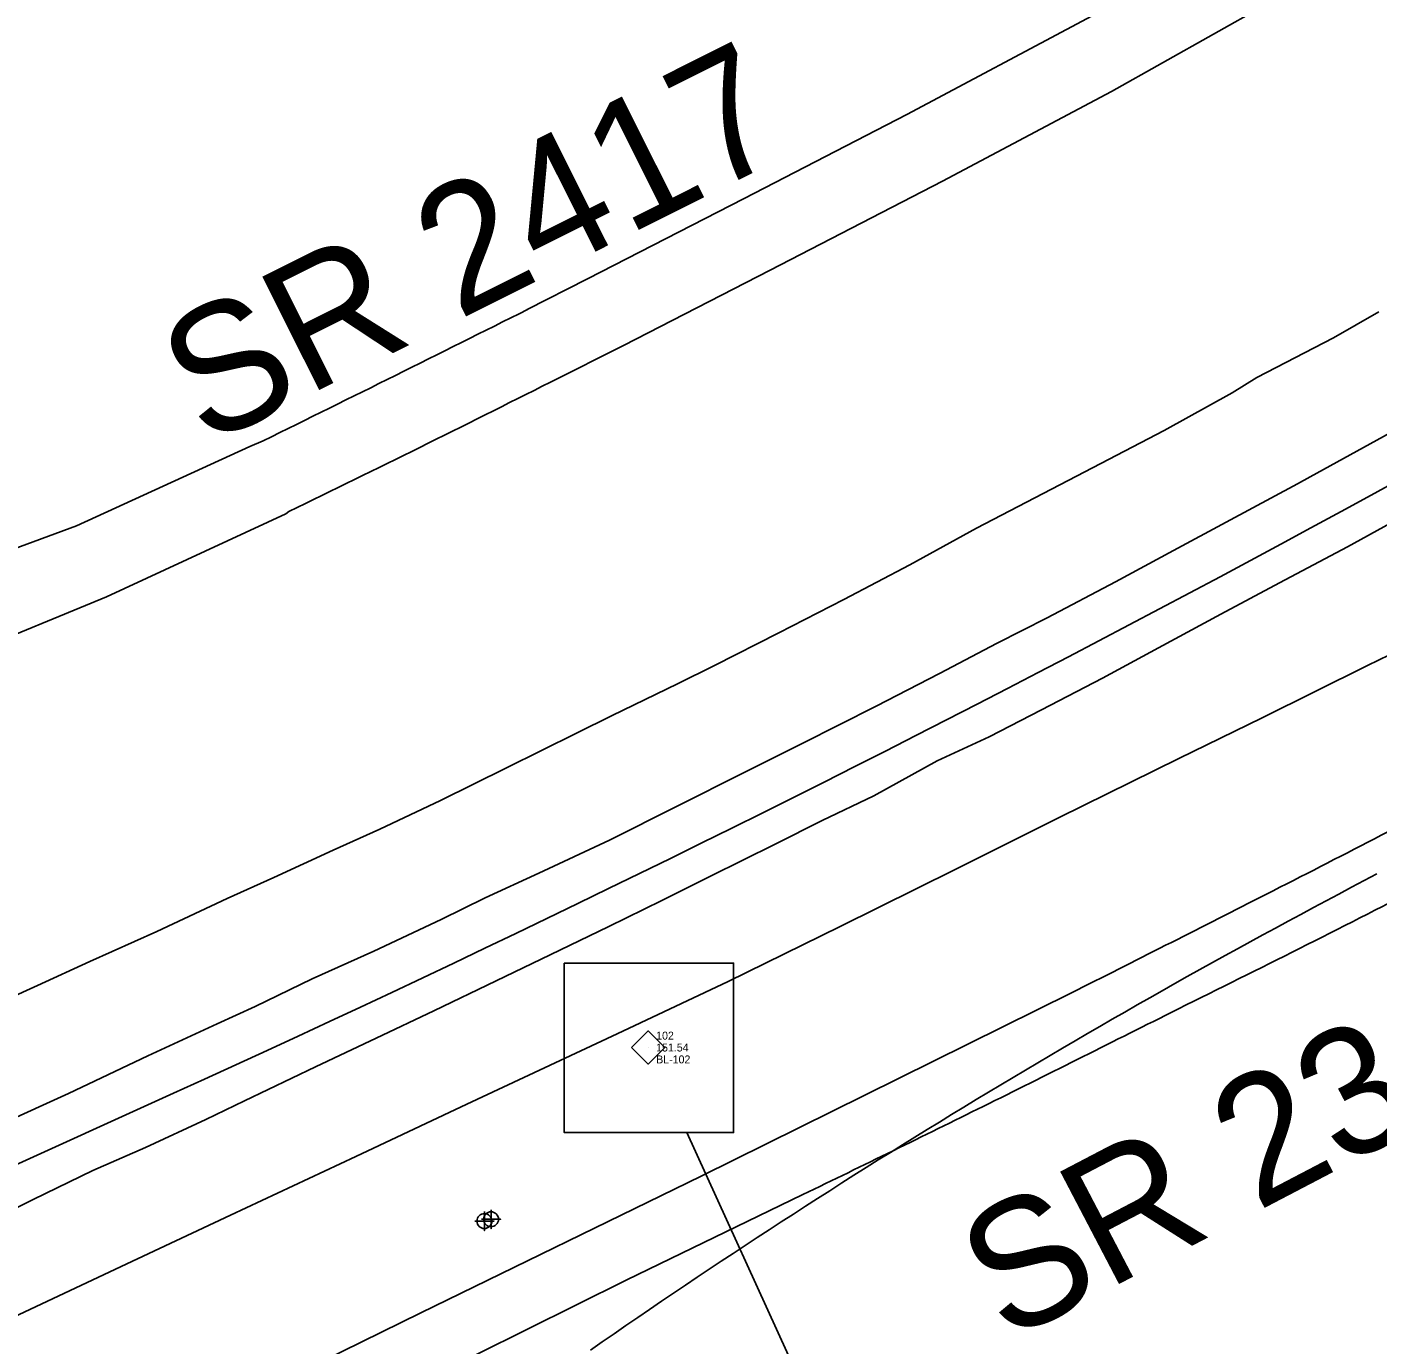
# Model space of a CAD drawing. Extents: x 2243531 to 2252747, y 658714 to 667210.
# Drawn here: x 2249746.9 to 2250172.5, y 663667.3 to 664082.4 of the extents above; entities that cross this region are included whole.
import ezdxf

# ---------------------------------------------------------------- set-up
doc = ezdxf.new("R2010")
doc.units = 0
for name, color, linetype in [('CTL NGS Horizontal CELL', 7, 'Continuous'), ('CTL Supplemental Horizontal and Vertical CELL', 7, 'Continuous'), ('CTL Supplemental Horizontal and Vertical Cogo Comment', 7, 'Continuous'), ('CTL Supplemental Horizontal and Vertical Cogo Elevation', 7, 'Continuous'), ('CTL Supplemental Horizontal and Vertical Cogo Number', 7, 'Continuous'), ('Exist DTM Regular Point CELL', 7, 'Continuous'), ('Exist Roads EOP', 7, 'Continuous'), ('Exist Roads EOP Text', 7, 'Continuous'), ('Prop Horizontal Alignment', 7, 'Continuous')]:
    doc.layers.add(name, color=color, linetype=linetype)

msp = doc.modelspace()

# ---------------------------------------------------------------- linework, layer by layer
at = {"layer": 'CTL NGS Horizontal CELL'}
msp.add_line((2249954.97, 663733.91), (2250093.64, 663429.6), dxfattribs=at)
at = {"layer": 'CTL Supplemental Horizontal and Vertical CELL'}
msp.add_line((2249942.75, 663760.73), (2249942.75, 663760.73), dxfattribs=at)
msp.add_line((2249942.75, 663760.73), (2249942.75, 663760.73), dxfattribs=at)
for points in [[(2249916.29, 663787.37), (2249969.66, 663787.37), (2249969.66, 663733.91), (2249916.29, 663733.91)], [(2249937.53, 663760.74), (2249942.78, 663765.99), (2249948.03, 663760.74), (2249942.78, 663755.49)]]:
    msp.add_lwpolyline(points, close=True, dxfattribs=at)
at = {"layer": 'Exist DTM Regular Point CELL'}
for points in [[(2249891.12, 663709), (2249891.12, 663703), (2249891.12, 663706), (2249894.12, 663706), (2249888.12, 663706)], [(2249893.22, 663709.61), (2249893.22, 663703.61), (2249893.22, 663706.61), (2249896.22, 663706.61), (2249890.22, 663706.61)]]:
    msp.add_lwpolyline(points, dxfattribs=at)
for centre in [(2249891.12, 663706), (2249893.22, 663706.61)]:
    msp.add_circle(centre, 2.34, dxfattribs=at)
at = {"layer": 'Exist Roads EOP'}
for points in [[(2250350.92, 664244.3), (2250304.23, 664213.76), (2250257.71, 664185.06), (2250201.23, 664151.95), (2250170.4, 664135.04), (2250126.46, 664109.78), (2250081.11, 664085.14), (2250024.28, 664054.88), (2249973, 664028.37), (2249923.63, 664003.06), (2249904.64, 663993.35)], [(2250350.92, 664244.3), (2250304.23, 664213.76), (2250257.71, 664185.06), (2250201.23, 664151.95), (2250170.4, 664135.04), (2250126.46, 664109.78), (2250081.11, 664085.14), (2250024.28, 664054.88), (2249973, 664028.37), (2249923.63, 664003.06), (2249904.64, 663993.35)], [(2250363.14, 664223.59), (2250317.79, 664195.69), (2250267.69, 664164.82), (2250214.57, 664134.24), (2250181.69, 664114.86), (2250136.97, 664089.2), (2250088.78, 664062.07), (2250035.53, 664033.88), (2249981.23, 664005.75), (2249934.93, 663982.02), (2249911.9, 663970.47)], [(2250363.14, 664223.59), (2250317.79, 664195.69), (2250267.69, 664164.82), (2250214.57, 664134.24), (2250181.69, 664114.86), (2250136.97, 664089.2), (2250088.78, 664062.07), (2250035.53, 664033.88), (2249981.23, 664005.75), (2249934.93, 663982.02), (2249911.9, 663970.47)], [(2250158.72, 663984.49), (2250173.08, 663992.65)], [(2250158.72, 663984.49), (2250173.08, 663992.65)], [(2250134.59, 663971.94), (2250158.72, 663984.49)], [(2250134.59, 663971.94), (2250126.82, 663967.1), (2250105.33, 663955.19), (2250085.39, 663944.79), (2250075.11, 663939.48), (2250046.26, 663924.42), (2250025.26, 663912.92), (2250004.43, 663901.99), (2249983.97, 663891.5), (2249963.67, 663881.2), (2249951.96, 663875.41), (2249931.42, 663865.38), (2249920.19, 663859.82), (2249898.1, 663848.94), (2249877.27, 663838.63), (2249858.19, 663829.56), (2249843.45, 663822.95), (2249824.73, 663814.35), (2249810.06, 663807.67), (2249787.9, 663797.34), (2249766.72, 663787.83), (2249750.29, 663780.29), (2249732.43, 663772.23)], [(2250134.59, 663971.94), (2250126.82, 663967.1), (2250105.33, 663955.19), (2250085.39, 663944.79), (2250075.11, 663939.48), (2250046.26, 663924.42), (2250025.26, 663912.92), (2250004.43, 663901.99), (2249983.97, 663891.5), (2249963.67, 663881.2), (2249951.96, 663875.41), (2249931.42, 663865.38), (2249920.19, 663859.82), (2249898.1, 663848.94), (2249877.27, 663838.63), (2249858.19, 663829.56), (2249843.45, 663822.95), (2249824.73, 663814.35), (2249810.06, 663807.67), (2249787.9, 663797.34), (2249766.72, 663787.83), (2249750.29, 663780.29), (2249732.43, 663772.23)], [(2250151.36, 663940.62), (2250178.7, 663955.71)], [(2249821.42, 663952.01), (2249817.14, 663950.24), (2249762.5, 663925.2), (2249719.52, 663909.32), (2249690.94, 663911.99), (2249672.57, 663925.89), (2249660.16, 663945.61)], [(2249821.42, 663952.01), (2249817.14, 663950.24), (2249762.5, 663925.2), (2249719.52, 663909.32), (2249690.94, 663911.99), (2249672.57, 663925.89), (2249660.16, 663945.61)], [(2250151.36, 663940.62), (2250147.39, 663938.44), (2250124.88, 663926.39), (2250108.36, 663917.42), (2250090.02, 663907.52), (2250068.46, 663896.14), (2250052.71, 663888.16), (2250034.57, 663878.68), (2250014.61, 663868.32), (2249991.28, 663856.62), (2249972.95, 663847.39), (2249951.67, 663836.73), (2249930.54, 663826.11), (2249908.26, 663815.71), (2249891.38, 663807.97), (2249877.49, 663801.04), (2249856.27, 663791.12), (2249836.88, 663782.34), (2249818.89, 663773.69), (2249806.84, 663768.16), (2249785, 663758.13), (2249759.98, 663746.21), (2249739.06, 663736.71)], [(2250151.36, 663940.62), (2250147.39, 663938.44), (2250124.88, 663926.39), (2250108.36, 663917.42), (2250090.02, 663907.52), (2250068.46, 663896.14), (2250052.71, 663888.16), (2250034.57, 663878.68), (2250014.61, 663868.32), (2249991.28, 663856.62), (2249972.95, 663847.39), (2249951.67, 663836.73), (2249930.54, 663826.11), (2249908.26, 663815.71), (2249891.38, 663807.97), (2249877.49, 663801.04), (2249856.27, 663791.12), (2249836.88, 663782.34), (2249818.89, 663773.69), (2249806.84, 663768.16), (2249785, 663758.13), (2249759.98, 663746.21), (2249739.06, 663736.71)], [(2250163.18, 663918.53), (2250192.4, 663934.62)], [(2249829.5, 663929.68), (2249828.55, 663928.96), (2249772.03, 663902.84), (2249728.05, 663884.69)], [(2249829.5, 663929.68), (2249828.55, 663928.96), (2249772.03, 663902.84), (2249728.05, 663884.69)], [(2250163.18, 663918.53), (2250141.76, 663907.17), (2250123.19, 663897.33), (2250103.59, 663886.75), (2250085.93, 663877.2), (2250066.71, 663867.19), (2250050.24, 663858.7), (2250033.81, 663851.08), (2250013.9, 663840.08), (2249997.54, 663832.27), (2249982.72, 663824.86), (2249962.36, 663814.71), (2249947.05, 663807.05), (2249930.38, 663798.85), (2249911.87, 663789.95), (2249894.79, 663781.72), (2249875.22, 663772.32), (2249857.01, 663763.64), (2249837.93, 663754.68), (2249815.49, 663743.88), (2249803.29, 663738.06), (2249784.26, 663729.26), (2249767.73, 663721.96), (2249748.92, 663712.77), (2249733.4, 663705.13)], [(2250163.18, 663918.53), (2250141.76, 663907.17), (2250123.19, 663897.33), (2250103.59, 663886.75), (2250085.93, 663877.2), (2250066.71, 663867.19), (2250050.24, 663858.7), (2250033.81, 663851.08), (2250013.9, 663840.08), (2249997.54, 663832.27), (2249982.72, 663824.86), (2249962.36, 663814.71), (2249947.05, 663807.05), (2249930.38, 663798.85), (2249911.87, 663789.95), (2249894.79, 663781.72), (2249875.22, 663772.32), (2249857.01, 663763.64), (2249837.93, 663754.68), (2249815.49, 663743.88), (2249803.29, 663738.06), (2249784.26, 663729.26), (2249767.73, 663721.96), (2249748.92, 663712.77), (2249733.4, 663705.13)], [(2249742.5, 663675.66), (2249776.59, 663691.66), (2249811.06, 663707.92), (2249850.56, 663726.37), (2249885.63, 663742.92), (2249932.97, 663765.08), (2249967.97, 663781.54), (2250003.28, 663798.87), (2250039.45, 663816.82), (2250072.29, 663833.2), (2250110.04, 663851.84), (2250136.3, 663864.69), (2250169.45, 663881.11), (2250179.91, 663886.23)], [(2249742.5, 663675.66), (2249776.59, 663691.66), (2249811.06, 663707.92), (2249850.56, 663726.37), (2249885.63, 663742.92), (2249932.97, 663765.08), (2249967.97, 663781.54), (2250003.28, 663798.87), (2250039.45, 663816.82), (2250072.29, 663833.2), (2250110.04, 663851.84), (2250136.3, 663864.69), (2250169.45, 663881.11), (2250179.91, 663886.23)], [(2250076.16, 663777.96), (2250011.04, 663745.73), (2249959.41, 663720.2), (2249871.12, 663677.1), (2249809.32, 663646.75), (2249741.67, 663615.28), (2249682.29, 663587.16), (2249593.6, 663545.55), (2249601.8, 663528.84), (2249642.54, 663547.1), (2249701.92, 663575.09), (2249765.85, 663604.94)], [(2250076.16, 663777.96), (2250011.04, 663745.73), (2249959.41, 663720.2), (2249871.12, 663677.1), (2249809.32, 663646.75), (2249741.67, 663615.28), (2249682.29, 663587.16), (2249593.6, 663545.55), (2249601.8, 663528.84), (2249642.54, 663547.1), (2249701.92, 663575.09), (2249765.85, 663604.94)], [(2249819.23, 663629.9), (2249873.17, 663656.29), (2249935.79, 663687.42), (2249991.5, 663714.36)], [(2249819.23, 663629.9), (2249873.17, 663656.29), (2249935.79, 663687.42), (2249991.5, 663714.36)]]:
    msp.add_lwpolyline(points, dxfattribs=at)
for centre, major_axis, ratio, start_param, end_param in [((2243811.47, 675999.36), (13052.38, 5841.5), 0.941395, 4.751862, 4.758361), ((2243811.47, 675999.36), (13052.38, 5841.5), 0.941395, 4.751862, 4.758361), ((2247879.75, 668075.13), (4790.63, 2522.22), 0.845906, 4.674336, 4.69132), ((2247879.75, 668075.13), (4790.63, 2522.22), 0.845906, 4.674336, 4.69132)]:
    msp.add_ellipse(centre, major_axis=major_axis, ratio=ratio, start_param=start_param, end_param=end_param, dxfattribs=at)
for points in [[(2250471.41, 664001.77), (2250423.97, 663971.94), (2250370.21, 663938.8), (2250319.7, 663908.28), (2250261.73, 663875.22), (2250203.37, 663843.21), (2250135.49, 663807.99), (2250076.16, 663777.96)], [(2250471.41, 664001.77), (2250423.97, 663971.94), (2250370.21, 663938.8), (2250319.7, 663908.28), (2250261.73, 663875.22), (2250203.37, 663843.21), (2250135.49, 663807.99), (2250076.16, 663777.96)], [(2249991.5, 663714.36), (2250048.33, 663742.16), (2250107.55, 663771.76), (2250183.63, 663810.1), (2250231.45, 663835.63), (2250295.43, 663870.92), (2250374.49, 663917.75)], [(2249991.5, 663714.36), (2250048.33, 663742.16), (2250107.55, 663771.76), (2250183.63, 663810.1), (2250231.45, 663835.63), (2250295.43, 663870.92), (2250374.49, 663917.75)]]:
    msp.add_spline(points, degree=3, dxfattribs=at)
at = {"layer": 'Prop Horizontal Alignment'}
msp.add_line((2247500.8, 662705.02), (2249793.08, 663746.29), dxfattribs=at)
for centre, radius, start, end in [((2247423.42, 668962.88), 5729.58, 294.43013, 308.28013), ((2251237.28, 661776.78), 2300, 117.57881, 124.80379)]:
    msp.add_arc(centre, radius, start, end, dxfattribs=at)

# ---------------------------------------------------------------- texts
at = {"layer": 'CTL Supplemental Horizontal and Vertical Cogo Comment'}
msp.add_text('BL-102', height=2.5, dxfattribs=at).set_placement((2249945.25, 663755.73))
msp.add_text('BL-102', height=2.5, dxfattribs=at).set_placement((2249945.25, 663755.73))
at = {"layer": 'CTL Supplemental Horizontal and Vertical Cogo Elevation'}
msp.add_text('151.54', height=2.5, dxfattribs=at).set_placement((2249945.25, 663759.48))
msp.add_text('151.54', height=2.5, dxfattribs=at).set_placement((2249945.25, 663759.48))
at = {"layer": 'CTL Supplemental Horizontal and Vertical Cogo Number'}
msp.add_text('102', height=2.5, dxfattribs=at).set_placement((2249945.25, 663763.23))
msp.add_text('102', height=2.5, dxfattribs=at).set_placement((2249945.25, 663763.23))
at = {"layer": 'Exist Roads EOP Text'}
for s, rotation, p in [('SR 2417', 26.6151, (2249803.22, 663950.02)), ('SR 2340', 27.616, (2250055.64, 663667.59))]:
    msp.add_text(s, height=40, rotation=rotation, dxfattribs=at).set_placement(p)

doc.saveas('drawing.dxf')
